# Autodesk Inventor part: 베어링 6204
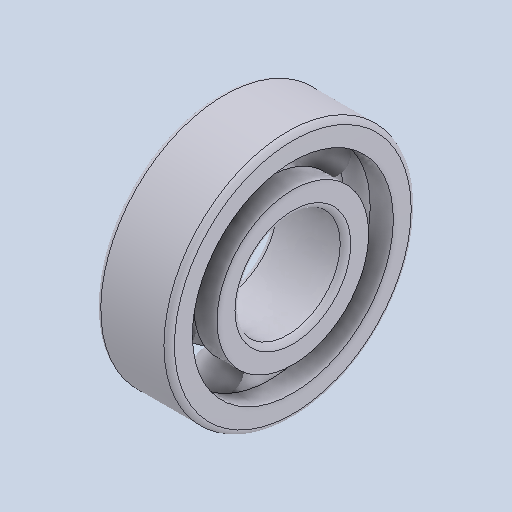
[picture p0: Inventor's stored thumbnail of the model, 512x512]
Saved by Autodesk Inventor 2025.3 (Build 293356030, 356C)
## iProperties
Created: 2025-08
Part Number: 베어링 6204
Material: 강철, 연강
Description: 깊은 그루브 볼 베어링
Document SubType Name: Modeling
Designer: user
Density: 7.86 g/cm^3
Appearance: 기본값
Sending System: Autodesk Inventor 2026
Preprocessor: ST-DEVELOPER v20.1
Author: jhkim
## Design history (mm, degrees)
sketch "스케치1"
  geometry: 1 further point
feature "Solid1"
feature "Solid1:1"
feature "Solid1:2"
feature "Solid1:3"
feature "Solid1:4"
feature "Solid1:5"
feature "Solid1:6"
feature "Solid1:7"
feature "Solid1:8"
node "솔리드1"
node "솔리드2"
node "솔리드3"
node "솔리드4"
node "솔리드5"
node "솔리드6"
node "솔리드7"
node "솔리드8"
node "솔리드9"
